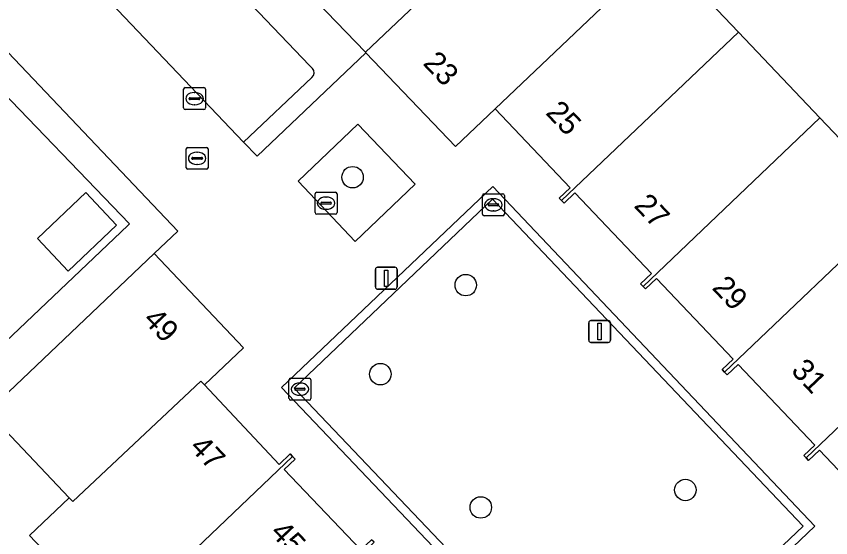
# Model space of a CAD drawing. Extents: x 162523 to 163266, y 381230 to 382050.
# Drawn here: x 163060.11 to 163097.26, y 381414.88 to 381438.66 of the extents above; entities that cross this region are included whole.
import ezdxf

# ---------------------------------------------------------------- set-up
doc = ezdxf.new("R2010")
doc.units = 0
for name, color, linetype in [('IMGEO_Boom', 7, 'Continuous'), ('IMGEO_Erf', 7, 'Continuous'), ('IMGEO_Groenvoorziening', 7, 'Continuous'), ('IMGEO_Kolk', 7, 'Continuous'), ('IMGEO_Lichtmast', 7, 'Continuous'), ('IMGEO_Pand', 7, 'Continuous'), ('IMGEO_Pand_nummerreeks', 7, 'Continuous'), ('IMGEO_Parkeervlak_open', 7, 'Continuous'), ('IMGEO_Rijbaan_lokaal_open', 7, 'Continuous'), ('IMGEO_Rioolput', 7, 'Continuous'), ('IMGEO_Voetpad_gesloten', 7, 'Continuous'), ('IMGEO_Voetpad_open', 7, 'Continuous')]:
    doc.layers.add(name, color=color, linetype=linetype)

msp = doc.modelspace()

# ---------------------------------------------------------------- linework, layer by layer
at = {"layer": 'IMGEO_Boom'}
for centre in [(163075.448, 381431.324), (163080.611, 381426.4), (163076.716, 381422.341), (163090.626, 381417.06), (163081.297, 381416.262)]:
    msp.add_circle(centre, 0.489, dxfattribs=at)
at = {"layer": 'IMGEO_Erf'}
msp.add_lwpolyline([(163083.008, 381514.758), (163040.612, 381474.54), (163040.156, 381474.136), (163076.039, 381437.018), (163085.444, 381445.952), (163089.529, 381441.652), (163093.052, 381437.943), (163096.767, 381434.031), (163100.485, 381430.118)], dxfattribs=at)
for points in [[(163065.276, 381429.193), (163058.711, 381436.008), (163058.639, 381435.939), (163054.732, 381432.221), (163055.408, 381431.518), (163051.291, 381427.599), (163047.385, 381423.88), (163043.482, 381420.165), (163039.559, 381416.43), (163035.487, 381412.554), (163034.791, 381413.286), (163030.875, 381409.558), (163030.817, 381409.502), (163037.334, 381402.645), (163065.195, 381429.116)], [(163061.073, 381428.524), (163063.282, 381430.629), (163064.687, 381429.134), (163062.483, 381427.04)], [(163072.065, 381403.062), (163068.326, 381406.987), (163064.626, 381410.871), (163060.708, 381414.985), (163062.522, 381416.706), (163058.801, 381420.628), (163058.749, 381420.683), (163051.544, 381413.821), (163078.037, 381385.91), (163085.304, 381392.789), (163085.216, 381392.882), (163081.494, 381396.792), (163079.681, 381395.066), (163075.788, 381399.153)]]:
    msp.add_lwpolyline(points, close=True, dxfattribs=at)
at = {"layer": 'IMGEO_Groenvoorziening'}
for points in [[(163073.591, 381435.864), (163070.478, 381432.925), (163071.096, 381432.278), (163076.058, 381436.998), (163076.039, 381437.018), (163040.156, 381474.136)], [(163058.244, 381452.35), (163073.489, 381436.42), (163073.617, 381436.286)]]:
    msp.add_lwpolyline(points, dxfattribs=at)
for points in [[(163075.693, 381433.739), (163072.972, 381431.149), (163075.57, 381428.397), (163078.306, 381431.003)], [(163096.002, 381415.414), (163081.828, 381430.321), (163072.791, 381421.702), (163086.952, 381406.828)]]:
    msp.add_lwpolyline(points, close=True, dxfattribs=at)
msp.add_arc((163073.387, 381436.088), 0.304, 312.3372, 40.6115, dxfattribs=at)
at = {"layer": 'IMGEO_Kolk'}
for p, q in [((163067.741, 381434.48), (163067.741, 381435.332)), ((163067.816, 381435.406), (163068.668, 381435.406)), ((163068.229, 381435.186), (163068.254, 381435.186)), ((163068.742, 381435.332), (163068.742, 381434.48)), ((163068, 381434.9), (163068, 381434.912)), ((163068.438, 381434.863), (163068.04, 381434.863)), ((163068.043, 381434.949), (163068.441, 381434.949)), ((163068.484, 381434.912), (163068.484, 381434.9)), ((163068.252, 381434.626), (163068.227, 381434.626)), ((163068.668, 381434.406), (163067.816, 381434.406)), ((163073.738, 381429.712), (163073.738, 381430.564)), ((163073.813, 381430.638), (163074.665, 381430.638)), ((163074.226, 381430.418), (163074.251, 381430.418)), ((163074.739, 381430.564), (163074.739, 381429.712)), ((163081.373, 381429.638), (163081.373, 381430.49)), ((163081.448, 381430.564), (163082.3, 381430.564)), ((163082.374, 381430.49), (163082.374, 381429.638)), ((163073.997, 381430.132), (163073.997, 381430.144)), ((163074.435, 381430.095), (163074.037, 381430.095)), ((163074.04, 381430.181), (163074.438, 381430.181)), ((163074.481, 381430.144), (163074.481, 381430.132)), ((163081.632, 381430.058), (163081.632, 381430.07)), ((163082.07, 381430.021), (163081.672, 381430.021)), ((163081.675, 381430.107), (163082.073, 381430.107)), ((163081.861, 381430.344), (163081.886, 381430.344)), ((163082.116, 381430.07), (163082.116, 381430.058)), ((163074.665, 381429.638), (163073.813, 381429.638)), ((163074.249, 381429.858), (163074.224, 381429.858)), ((163081.884, 381429.784), (163081.859, 381429.784)), ((163082.3, 381429.564), (163081.448, 381429.564)), ((163072.549, 381421.23), (163072.549, 381422.082)), ((163072.624, 381422.156), (163073.476, 381422.156)), ((163073.037, 381421.936), (163073.062, 381421.936)), ((163073.55, 381422.082), (163073.55, 381421.23)), ((163072.808, 381421.65), (163072.808, 381421.662)), ((163073.246, 381421.613), (163072.848, 381421.613)), ((163072.851, 381421.699), (163073.249, 381421.699)), ((163073.292, 381421.662), (163073.292, 381421.65)), ((163073.476, 381421.156), (163072.624, 381421.156)), ((163073.06, 381421.376), (163073.035, 381421.376))]:
    msp.add_line(p, q, dxfattribs=at)
for points in [[(163067.741, 381434.48), (163067.741, 381435.332)], [(163067.816, 381435.406), (163068.668, 381435.406)], [(163068.742, 381435.332), (163068.742, 381434.48)], [(163068.668, 381434.406), (163067.816, 381434.406)], [(163073.738, 381429.712), (163073.738, 381430.564)], [(163073.813, 381430.638), (163074.665, 381430.638)], [(163074.739, 381430.564), (163074.739, 381429.712)], [(163081.373, 381429.638), (163081.373, 381430.49)], [(163081.448, 381430.564), (163082.3, 381430.564)], [(163082.374, 381430.49), (163082.374, 381429.638)], [(163074.665, 381429.638), (163073.813, 381429.638)], [(163082.3, 381429.564), (163081.448, 381429.564)], [(163072.549, 381421.23), (163072.549, 381422.082)], [(163072.624, 381422.156), (163073.476, 381422.156)], [(163073.55, 381422.082), (163073.55, 381421.23)], [(163073.476, 381421.156), (163072.624, 381421.156)]]:
    msp.add_lwpolyline(points, dxfattribs=at)
for centre, radius, start, end in [((163067.818, 381435.33), 0.0765, 91.552, 178.448), ((163067.818, 381435.33), 0.0765, 91.552, 178.448), ((163068.666, 381435.33), 0.0765, 1.552, 88.448), ((163068.666, 381435.33), 0.0765, 1.552, 88.448), ((163068.04, 381434.909), 0.0403, 85.8775, 175.7526), ((163068.037, 381434.899), 0.0366, 178.938, 274.7102), ((163068.441, 381434.906), 0.043, 264.8664, 352.4533), ((163068.445, 381434.911), 0.0386, 1.7309, 96.639), ((163067.818, 381434.482), 0.0765, 181.552, 268.448), ((163067.818, 381434.482), 0.0765, 181.552, 268.448), ((163068.666, 381434.482), 0.0765, 271.552, 358.448), ((163068.666, 381434.482), 0.0765, 271.552, 358.448), ((163073.815, 381430.562), 0.0765, 91.552, 178.448), ((163073.815, 381430.562), 0.0765, 91.552, 178.448), ((163074.663, 381430.562), 0.0765, 1.552, 88.448), ((163074.663, 381430.562), 0.0765, 1.552, 88.448), ((163081.45, 381430.488), 0.0765, 91.552, 178.448), ((163081.45, 381430.488), 0.0765, 91.552, 178.448), ((163082.298, 381430.488), 0.0765, 1.552, 88.448), ((163082.298, 381430.488), 0.0765, 1.552, 88.448), ((163074.037, 381430.141), 0.0403, 85.8775, 175.7526), ((163074.034, 381430.131), 0.0366, 178.938, 274.7102), ((163074.438, 381430.138), 0.043, 264.8664, 352.4533), ((163074.442, 381430.143), 0.0386, 1.7309, 96.639), ((163081.672, 381430.067), 0.0403, 85.8775, 175.7526), ((163081.669, 381430.057), 0.0366, 178.938, 274.7102), ((163082.073, 381430.064), 0.043, 264.8664, 352.4533), ((163082.077, 381430.069), 0.0386, 1.7309, 96.639), ((163073.815, 381429.714), 0.0765, 181.552, 268.448), ((163073.815, 381429.714), 0.0765, 181.552, 268.448), ((163074.663, 381429.714), 0.0765, 271.552, 358.448), ((163074.663, 381429.714), 0.0765, 271.552, 358.448), ((163081.45, 381429.64), 0.0765, 181.552, 268.448), ((163081.45, 381429.64), 0.0765, 181.552, 268.448), ((163082.298, 381429.64), 0.0765, 271.552, 358.448), ((163082.298, 381429.64), 0.0765, 271.552, 358.448), ((163072.626, 381422.08), 0.0765, 91.552, 178.448), ((163072.626, 381422.08), 0.0765, 91.552, 178.448), ((163073.474, 381422.08), 0.0765, 1.552, 88.448), ((163073.474, 381422.08), 0.0765, 1.552, 88.448), ((163072.848, 381421.659), 0.0403, 85.8775, 175.7526), ((163072.845, 381421.649), 0.0366, 178.938, 274.7102), ((163073.249, 381421.656), 0.043, 264.8664, 352.4533), ((163073.253, 381421.661), 0.0386, 1.7309, 96.639), ((163072.626, 381421.232), 0.0765, 181.552, 268.448), ((163072.626, 381421.232), 0.0765, 181.552, 268.448), ((163073.474, 381421.232), 0.0765, 271.552, 358.448), ((163073.474, 381421.232), 0.0765, 271.552, 358.448)]:
    msp.add_arc(centre, radius, start, end, dxfattribs=at)
for centre, major_axis, ratio, start_param, end_param in [((163068.228, 381434.906), (-0.387, 0.002), 0.722429, 4.712389, 7.853982), ((163068.253, 381434.906), (-0.39, 0.002), 0.717154, 1.570796, 4.712389), ((163074.225, 381430.138), (-0.387, 0.002), 0.722429, 4.712389, 7.853982), ((163074.25, 381430.138), (-0.39, 0.002), 0.717154, 1.570796, 4.712389), ((163081.86, 381430.064), (-0.387, 0.002), 0.722429, 4.712389, 7.853982), ((163081.885, 381430.064), (-0.39, 0.002), 0.717154, 1.570796, 4.712389), ((163073.036, 381421.656), (-0.387, 0.002), 0.722429, 4.712389, 7.853982), ((163073.061, 381421.656), (-0.39, 0.002), 0.717154, 1.570796, 4.712389)]:
    msp.add_ellipse(centre, major_axis=major_axis, ratio=ratio, start_param=start_param, end_param=end_param, dxfattribs=at)
at = {"layer": 'IMGEO_Lichtmast'}
for p, q in [((163076.491, 381426.316), (163076.491, 381427.116)), ((163076.491, 381427.116), (163076.491, 381426.316)), ((163076.591, 381427.216), (163077.381, 381427.216)), ((163077.381, 381427.216), (163076.591, 381427.216)), ((163077.481, 381427.116), (163077.481, 381426.316)), ((163077.481, 381426.316), (163077.481, 381427.116)), ((163077.381, 381426.216), (163076.591, 381426.216)), ((163076.591, 381426.216), (163077.381, 381426.216)), ((163086.319, 381424.787), (163087.109, 381424.787)), ((163087.109, 381424.787), (163086.319, 381424.787)), ((163086.219, 381423.887), (163086.219, 381424.687)), ((163086.219, 381424.687), (163086.219, 381423.887)), ((163087.209, 381424.687), (163087.209, 381423.887)), ((163087.209, 381423.887), (163087.209, 381424.687)), ((163087.109, 381423.787), (163086.319, 381423.787)), ((163086.319, 381423.787), (163087.109, 381423.787))]:
    msp.add_line(p, q, dxfattribs=at)
for points in [[(163076.911, 381427.091), (163077.061, 381427.091), (163077.061, 381426.341), (163076.911, 381426.341), (163076.911, 381427.091)], [(163086.639, 381424.662), (163086.789, 381424.662), (163086.789, 381423.912), (163086.639, 381423.912), (163086.639, 381424.662)]]:
    msp.add_lwpolyline(points, dxfattribs=at)
for centre, start, end in [((163076.591, 381427.116), 90, 180), ((163076.591, 381427.116), 90, 180), ((163077.381, 381427.116), 0, 90), ((163077.381, 381427.116), 360, 90), ((163076.591, 381426.316), 180, 270), ((163076.591, 381426.316), 180, 270), ((163077.381, 381426.316), 270, 0), ((163077.381, 381426.316), 270, 0), ((163086.319, 381424.687), 90, 180), ((163086.319, 381424.687), 90, 180), ((163087.109, 381424.687), 0, 90), ((163087.109, 381424.687), 360, 90), ((163086.319, 381423.887), 180, 270), ((163086.319, 381423.887), 180, 270), ((163087.109, 381423.887), 270, 0), ((163087.109, 381423.887), 270, 0)]:
    msp.add_arc(centre, 0.1, start, end, dxfattribs=at)
at = {"layer": 'IMGEO_Pand'}
for points in [[(163089.529, 381441.652), (163085.444, 381445.952), (163076.039, 381437.018), (163076.058, 381436.998), (163080.137, 381432.722), (163081.945, 381434.441)], [(163093.052, 381437.943), (163089.529, 381441.652), (163081.945, 381434.441), (163085.369, 381430.841), (163084.871, 381430.37), (163084.983, 381430.253)], [(163096.767, 381434.031), (163093.052, 381437.943), (163084.983, 381430.253), (163085.094, 381430.136), (163085.592, 381430.606), (163089.085, 381426.933), (163088.587, 381426.46), (163088.698, 381426.344)], [(163100.485, 381430.118), (163096.767, 381434.031), (163088.698, 381426.344), (163088.808, 381426.228), (163089.304, 381426.703), (163092.808, 381423.018), (163092.306, 381422.547), (163092.418, 381422.43)], [(163064.687, 381429.134), (163063.282, 381430.629), (163061.073, 381428.524), (163062.483, 381427.04)], [(163104.2, 381426.206), (163104.037, 381426.378), (163100.485, 381430.118), (163092.418, 381422.43), (163092.529, 381422.313), (163093.03, 381422.785), (163096.53, 381419.105), (163096.023, 381418.636), (163096.135, 381418.519)], [(163070.475, 381423.547), (163066.405, 381427.84), (163058.801, 381420.628), (163062.522, 381416.706), (163062.691, 381416.528), (163068.531, 381422.026), (163068.693, 381421.855)], [(163108.981, 381422.924), (163104.909, 381427.207), (163104.037, 381426.378), (163104.2, 381426.206), (163096.135, 381418.519), (163096.247, 381418.401), (163096.749, 381418.875), (163100.185, 381415.262), (163100.349, 381415.09), (163106.108, 381420.567), (163106.288, 381420.378)], [(163072.711, 381418.582), (163072.597, 381418.701), (163072.106, 381418.229), (163068.693, 381421.855), (163068.531, 381422.026), (163062.691, 381416.528), (163062.522, 381416.706), (163060.708, 381414.985), (163064.626, 381410.871)], [(163076.429, 381414.676), (163076.317, 381414.793), (163075.823, 381414.324), (163072.331, 381417.993), (163072.824, 381418.463), (163072.711, 381418.582), (163064.626, 381410.871), (163068.326, 381406.987)]]:
    msp.add_lwpolyline(points, close=True, dxfattribs=at)
at = {"layer": 'IMGEO_Parkeervlak_open'}
for points in [[(163073.617, 381436.286), (163073.489, 381436.42), (163058.244, 381452.35)], [(163054.489, 381449.708), (163070.478, 381432.925), (163073.591, 381435.864)]]:
    msp.add_lwpolyline(points, dxfattribs=at)
msp.add_arc((163073.387, 381436.088), 0.304, 312.3372, 40.6115, dxfattribs=at)
at = {"layer": 'IMGEO_Rijbaan_lokaal_open'}
for points in [[(163031.899, 381466.309), (163067.48, 381428.86), (163066.405, 381427.84), (163070.475, 381423.547), (163068.693, 381421.855), (163072.106, 381418.229), (163072.597, 381418.701), (163072.711, 381418.582), (163072.824, 381418.463), (163072.331, 381417.993), (163075.823, 381414.324)], [(163100.185, 381415.262), (163096.749, 381418.875), (163096.247, 381418.401), (163096.135, 381418.519), (163096.023, 381418.636), (163096.53, 381419.105), (163093.03, 381422.785), (163092.529, 381422.313), (163092.418, 381422.43), (163092.306, 381422.547), (163092.808, 381423.018), (163089.304, 381426.703), (163088.808, 381426.228), (163088.698, 381426.344), (163088.587, 381426.46), (163089.085, 381426.933), (163085.592, 381430.606), (163085.094, 381430.136), (163084.983, 381430.253), (163084.871, 381430.37), (163085.369, 381430.841), (163081.945, 381434.441), (163080.137, 381432.722), (163076.058, 381436.998), (163071.096, 381432.278), (163070.478, 381432.925), (163054.489, 381449.708)]]:
    msp.add_lwpolyline(points, dxfattribs=at)
for points in [[(163075.693, 381433.739), (163078.306, 381431.003), (163075.57, 381428.397), (163072.972, 381431.149)], [(163072.212, 381421.739), (163081.847, 381430.905), (163096.528, 381415.411), (163086.945, 381406.255)]]:
    msp.add_lwpolyline(points, close=True, dxfattribs=at)
at = {"layer": 'IMGEO_Rioolput'}
for p, q in [((163067.859, 381431.757), (163067.859, 381432.609)), ((163067.934, 381432.683), (163068.786, 381432.683)), ((163068.86, 381432.609), (163068.86, 381431.757)), ((163068.161, 381432.226), (163068.559, 381432.226)), ((163068.347, 381432.463), (163068.372, 381432.463)), ((163068.118, 381432.177), (163068.118, 381432.189)), ((163068.556, 381432.14), (163068.158, 381432.14)), ((163068.37, 381431.903), (163068.345, 381431.903)), ((163068.602, 381432.189), (163068.602, 381432.177)), ((163068.786, 381431.683), (163067.934, 381431.683))]:
    msp.add_line(p, q, dxfattribs=at)
for points in [[(163067.859, 381431.757), (163067.859, 381432.609)], [(163067.934, 381432.683), (163068.786, 381432.683)], [(163068.86, 381432.609), (163068.86, 381431.757)], [(163068.786, 381431.683), (163067.934, 381431.683)]]:
    msp.add_lwpolyline(points, dxfattribs=at)
for centre, radius, start, end in [((163067.936, 381432.607), 0.0765, 91.552, 178.448), ((163067.936, 381432.607), 0.0765, 91.552, 178.448), ((163068.784, 381432.607), 0.0765, 1.552, 88.448), ((163068.784, 381432.607), 0.0765, 1.552, 88.448), ((163068.158, 381432.186), 0.0403, 85.8775, 175.7526), ((163068.563, 381432.188), 0.0386, 1.7309, 96.639), ((163068.155, 381432.176), 0.0366, 178.938, 274.7102), ((163068.559, 381432.183), 0.043, 264.8664, 352.4533), ((163067.936, 381431.759), 0.0765, 181.552, 268.448), ((163067.936, 381431.759), 0.0765, 181.552, 268.448), ((163068.784, 381431.759), 0.0765, 271.552, 358.448), ((163068.784, 381431.759), 0.0765, 271.552, 358.448)]:
    msp.add_arc(centre, radius, start, end, dxfattribs=at)
for centre, major_axis, ratio, start_param, end_param in [((163068.346, 381432.183), (-0.387, 0.002), 0.722429, 4.712389, 7.853982), ((163068.371, 381432.183), (-0.39, 0.002), 0.717154, 1.570796, 4.712389)]:
    msp.add_ellipse(centre, major_axis=major_axis, ratio=ratio, start_param=start_param, end_param=end_param, dxfattribs=at)
at = {"layer": 'IMGEO_Voetpad_gesloten'}
for points in [[(163072.212, 381421.739), (163086.945, 381406.255), (163096.528, 381415.411), (163081.847, 381430.905)], [(163096.002, 381415.414), (163086.952, 381406.828), (163072.791, 381421.702), (163081.828, 381430.321)]]:
    msp.add_lwpolyline(points, close=True, dxfattribs=at)
at = {"layer": 'IMGEO_Voetpad_open'}
msp.add_lwpolyline([(163078.037, 381385.91), (163051.544, 381413.821), (163058.749, 381420.683), (163058.801, 381420.628), (163066.405, 381427.84), (163067.48, 381428.86), (163031.899, 381466.309), (163030.823, 381465.305), (163035.81, 381460.122), (163035.736, 381460.052), (163042.948, 381452.458), (163043.031, 381452.537), (163046.576, 381448.819), (163046.493, 381448.74), (163051.404, 381443.564), (163058.639, 381435.939), (163058.711, 381436.008), (163065.276, 381429.193), (163065.195, 381429.116), (163037.334, 381402.645), (163035.996, 381401.387), (163036.717, 381400.603), (163037.105, 381400.96), (163075.261, 381360.801)], dxfattribs=at)

# ---------------------------------------------------------------- texts
at = {"layer": 'IMGEO_Pand_nummerreeks'}
for s, rotation, p in [('23', 313.6477, (163078.62, 381436.486)), ('25', 313.5675, (163084.215, 381434.23)), ('27', 313.5618, (163088.244, 381429.993)), ('29', 313.556, (163091.804, 381426.25)), ('49', 313.4701, (163065.855, 381424.786)), ('31', 313.5618, (163095.405, 381422.464)), ('47', 313.2696, (163067.975, 381418.97)), ('45', 313.5847, (163071.654, 381415.078))]:
    msp.add_text(s, height=1, rotation=rotation, dxfattribs=at).set_placement(p)

doc.saveas('drawing.dxf')
